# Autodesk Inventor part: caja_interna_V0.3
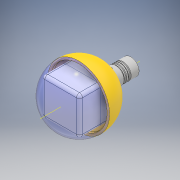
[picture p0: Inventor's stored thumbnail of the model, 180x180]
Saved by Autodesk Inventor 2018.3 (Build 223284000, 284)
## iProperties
Created: 2018-09
Part Number: caja_interna_V0.3
Material: Generic
Document SubType Name: Modeling
Designer: Gordillo
Density: 1 g/cm^3
Appearance: Default
Author: Gordillo
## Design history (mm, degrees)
sketch "Sketch1"
  geometry: L1 (125, 125)-(-125, 125); L2 (-125, 125)-(-125, -125); L3 (-125, -125)-(125, -125); L4 (125, -125)-(125, 125); L5 (-175, 0)-(175, 0) reference; L6 (0, -175)-(0, 175) reference; 1 further point
  constraints: 8 end point, 2 parallel, 1 horizontal, 1 perpendicular, 2 other
  dimensions: "d0" = 250 distance of L3.end L2.end; "d1" = 250 distance of L2.end L1.end
extrude "Extrusion1" new body sketch "Sketch1" distance "d2" = 220; taper "d3" = 0 deg
fillet "Fillet1" dims "d5" = 20
sketch "Sketch2"
  geometry: L1 (20, 125)-(220, 125) reference; L2 (120, 125)-(120, -125); L3 (220, -125)-(20, -125) reference; L4 (120, 125)-(120, 205); L5 (120, 0)-(-80, 0); L6 (-153.152, 0)-(282.192, 0) reference; A1 r 203.001 centre (122.991, 2.021) between (120, 205) and (-80, 0); 1 further point
  constraints: 6 end point, 3 midpoint, 2 point on circle, 1 centre point, 1 horizontal, 1 vertical
  dimensions: "d6" = 200 distance of L5.start L5.end; "d8" = 80 distance of L2.start L4.end
revolve "Revolution1" sketch "Sketch2" stored, may be unused: angle "d9" = 90 deg
combine "Combine1"
shell "Shell2" dims "d10" = 25
sketch "Sketch3"
  geometry: L1 (100, 100)-(100, -100) reference; L2 (100, -100)-(-100, -100) reference; L3 (-100, -100)-(-100, 100) reference; L4 (-100, 100)-(100, 100) reference; L5 (105, 125)-(-105, 125) reference; L6 (-125, 105)-(-125, -105) reference; L7 (-105, -125)-(105, -125) reference; L8 (125, -105)-(125, 105) reference; L9 (-105, 125)-(105, 125) reference; L10 (125, 105)-(125, -105) reference; L11 (105, -125)-(-105, -125) reference; L12 (-125, -105)-(-125, 105) reference; L13 (-105, 125)-(105, 125) reference; L14 (105, 125)-(-105, 125); L15 (-105, 125)-(-125, 105); L16 (-125, -105)-(-125, 105) reference; L17 (-125, -105)-(-105, -125); L18 (125, 105)-(125, -105) reference; L19 (105, -125)-(125, -105); L20 (125, -105)-(125, 105); L21 (-125, 105)-(-105, 105) reference; L22 (-125, 105)-(-125, -105); L23 (-105, -125)-(105, -125); C1 r 205 at (0, 0) reference; C2 r 189 at (0, 0); C3 r 205 at (0, 0) reference; A1 r 20 centre (105, 105) between (125, 105) and (105, 125) reference; A2 r 20 centre (-105, 105) between (-105, 125) and (-125, 105) reference; A3 r 20 centre (-105, -105) between (-125, -105) and (-105, -125) reference; A4 r 20 centre (105, -105) between (105, -125) and (125, -105) reference; A5 r 20 centre (-105, 105) between (-105, 125) and (-125, 105) reference; A6 r 20 centre (105, 105) between (125, 105) and (105, 125) reference; A7 r 20 centre (105, -105) between (105, -125) and (125, -105) reference; A8 r 20 centre (-105, -105) between (-125, -105) and (-105, -125) reference; A9 r 20 centre (105, 105) between (125, 105) and (105, 125) reference; A10 r 20 centre (105, 105) between (125, 105) and (105, 125); A11 r 20 centre (105, -105) between (105, -125) and (125, -105) reference; A12 r 20 centre (105, -105) between (105, -125) and (125, -105); A13 r 20 centre (-105, -105) between (-125, -105) and (-105, -125); A14 r 20 centre (-105, 105) between (-105, 125) and (-125, 105) reference; A15 r 20 centre (-105, 105) between (-105, 125) and (-125, 105); A16 r 20 centre (-105, -105) between (-125, -105) and (-105, -125); A17 r 20 centre (-105, -105) between (-125, -105) and (-105, -125); A18 r 20 centre (105, -105) between (105, -125) and (125, -105); A19 r 20 centre (-105, -105) between (-125, -105) and (-105, -125) reference; A20 r 20 centre (-105, -105) between (-125, -105) and (-105, -125); 1 further point
  constraints: 16 point on circle, 14 end point, 9 centre point, 3 perpendicular, 3 tangent, 2 collinear, 1 concentric, 1 vertical
  dimensions: "d11" = 16 radial gap between concentric circles of C1 C2
extrude "Extrusion2" join sketch "Sketch3" distance "d12" = 20; taper "d13" = 0 deg
sketch "Sketch4"
  geometry: L1 (189, 140)-(-189, 140) reference; L2 (205, 120)-(-205, 120) reference; L3 (189, 120)-(189, 140) reference; L4 (189, 140)-(-189, 140) reference; L5 (-189, 120)-(189, 120) reference; L6 (-125, 20)-(-125, 220) reference; L7 (-125, 220)-(-105, 220) reference; L8 (-205, 120)-(-189, 120); L9 (-189, 120)-(-189, 140); L10 (205, 120)-(-205, 120) reference; L11 (-189, 140)-(-125, 140); L12 (0, 120)-(0, 320); L13 (-125, 140)-(0, 140); L14 (0, -168.98)-(0, 453.807) reference; L15 (0, 304)-(-55, 304); L16 (-55, 304)-(-55, 315.014); L17 (0, 304)-(0, 298); L18 (0, 304)-(-55, 304); L19 (-55, 304)-(-55, 315.014); L20 (-87, 304.444)-(-67, 304.444); L21 (-67, 304.444)-(-67, 311.765); A1 r 195 centre (-10.071, 125.26) between (0, 320) and (-205, 120); A2 r 177.861 centre (-12.205, 120.558) between (0, 298) and (-189, 140); A3 r 195 centre (-10.071, 125.26) between (-55, 315.014) and (-205, 120); A4 r 177.861 centre (-12.205, 120.558) between (0, 298) and (-189, 140); 2 further points
  constraints: 24 end point, 11 point on circle, 5 point on line, 4 centre point, 4 perpendicular, 3 vertical, 2 collinear, 2 concentric, 2 midpoint, 1 horizontal
  dimensions: "d14" = 200 distance of L12.start L12.end; "d15" = 195 radius of A1; "d16" = 22 distance of L12.end L17.end; "d26" = 55 distance of L15.start L15.end; "d27" = 16 distance from line of L12.end L15; "d28" = 177.86112 radius of A2; "d30" = 12 distance between parallel lines of L16 L21; "d31" = 20 distance of L20.start L20.end
  node "Projected Loop3"
  node "Projected Loop4"
derived "tubo_electrovalvula_V0.1.ipt"
feature "Move Body1"
feature "Move Body3"
revolve "Revolution4" stored, may be unused: angle "d32" = 90 deg
workplane "Work Plane1"
sketch "Sketch5"
  geometry: L1 (67, 21.765)-(-67, 21.765) reference; L2 (0, 21.765)-(0, 14.444); L3 (67, 14.444)-(-67, 14.444) reference; 2 further points
  constraints: 3 midpoint, 2 end point
hole "Hole1" sketch "Sketch5" at (0, 18.105) diameter "d33" = 3; stored, may be unused: countersink angle "d37" = 90 deg, drill point angle "d39" = 118 deg; dims "d34" = 6, "d35" = 4, "d36" = 2, "d38" = 6
sketch "Sketch6"
  geometry: C1 r 1.5 at (0, 18.105); A1 r 1.5 centre (0, 18.105) between (0, 16.605) and (0, 19.605) reference; A2 r 1.5 centre (0, 18.105) between (0, 16.605) and (0, 19.605) reference; 1 further point
  constraints: 1 centre point, 1 coincident, 1 concentric
extrude "Extrusion3" cut sketch "Sketch6" distance "d40" = 20; taper "d41" = 0 deg
pattern_circular "Circular Pattern1" dims angle "d43" = 360 deg
node "cajacorchopan"
node "semicirculo_inferior"
node "Projected Loop1"
node "Projected Loop2"
feature "Solid1::tubo_electrovalvula_V0.1.ipt" dims "d18" = 10
tag "TaggingFeature1"
node "semicirculo_superior"
node "tubo inflado"
other parameters: "d19" = 270 deg, "d23" = 0
